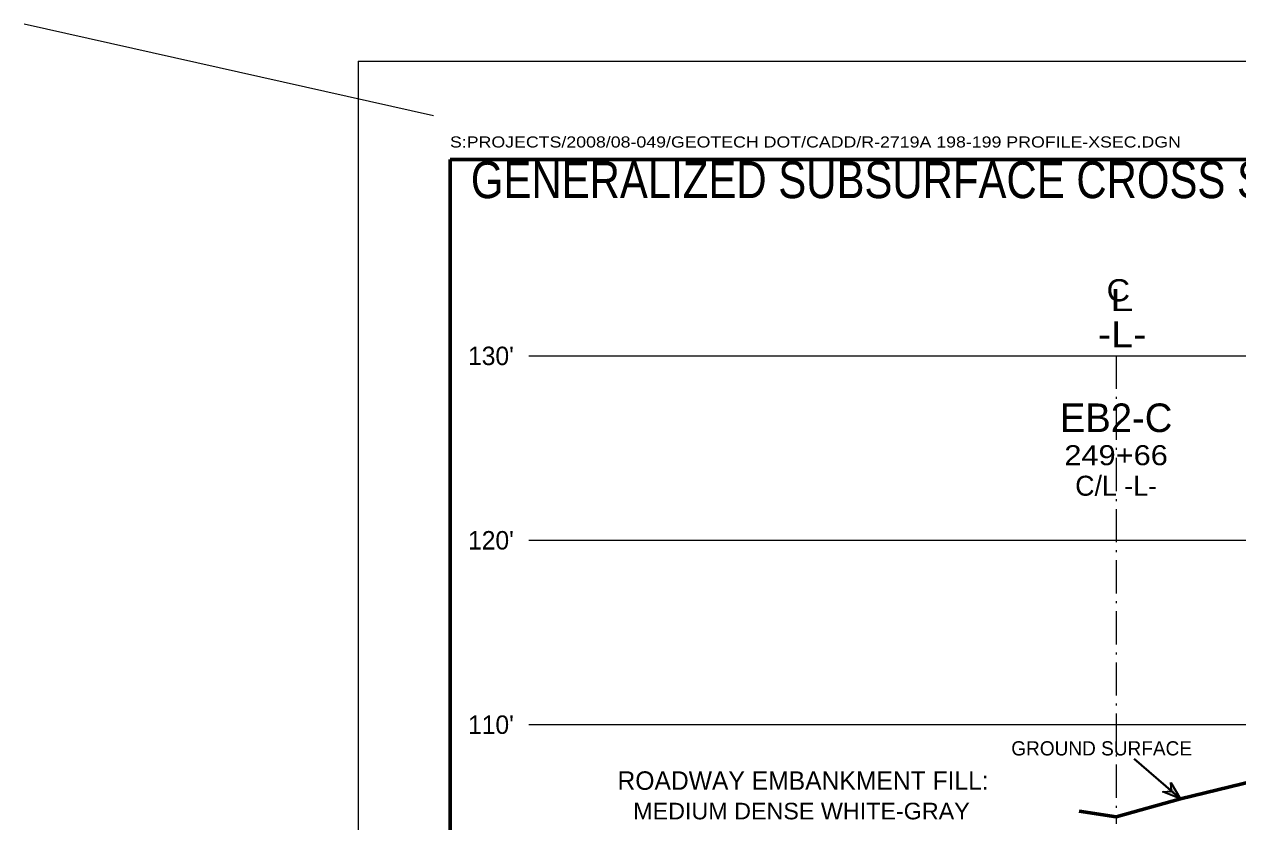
# Model space of a CAD drawing. Extents: x -76 to 974, y -1080 to -735.
# Drawn here: x 837.5 to 903.4, y -927.4 to -884.1 of the extents above; entities that cross this region are included whole.
import ezdxf
from ezdxf.enums import TextEntityAlignment as Align

# ---------------------------------------------------------------- set-up
doc = ezdxf.new("R2010")
doc.units = 0
doc.header["$LTSCALE"] = 0.36
doc.linetypes.add('DOT_DASHED', pattern=[7.7, 5, -1.2, 0.3, -1.2])
doc.linetypes.add('LONG_DASHED', pattern=[7.5, 6, -1.5])
for name, color, linetype, lineweight in [('10', 7, 'Continuous', 35), ('27', 7, 'Continuous', 40), ('28', 7, 'LONG_DASHED', 60), ('63', 7, 'Continuous', 35), ('7', 7, 'Continuous', 13)]:
    doc.layers.add(name, color=color, linetype=linetype, lineweight=lineweight)
doc.layers.add('29', color=7, linetype='Continuous')

msp = doc.modelspace()

# ---------------------------------------------------------------- hatches: boundary and pattern name
at = {"layer": '10'}
msp.add_hatch(color=256, dxfattribs=at).paths.add_polyline_path([(899.7198, -925.2326), (900.2574, -926.1302), (899.289, -925.7348), (899.7554, -925.699)])

# ---------------------------------------------------------------- linework, layer by layer
msp.add_lwpolyline([(899.7198, -925.2326), (900.2574, -926.1302), (899.289, -925.7348), (899.7554, -925.699)], close=True, dxfattribs=at)
at = {"layer": '27', "lineweight": 13}
msp.add_line((859.7247, -889.0898), (837.5348, -884.1181), dxfattribs=at)
at = {"layer": '27'}
msp.add_line((900.2577, -926.13), (897.7373, -923.9477), dxfattribs=at)
at = {"layer": '28', "linetype": 'Continuous'}
msp.add_lwpolyline([(894.7577, -926.79), (896.7577, -927.09), (900.2577, -926.13), (904.2577, -925.15), (927.7577, -925.74), (927.7577, -925.23), (931.7577, -925.24), (937.2577, -926.05), (942.7577, -926.96)], dxfattribs=at)
at = {"layer": '63', "lineweight": 13}
for q in [(855.6417, -1056.1123), (965.6417, -886.1123)]:
    msp.add_line((855.6417, -886.1123), q, dxfattribs=at)
at = {"layer": '63', "lineweight": 60}
for p in [(860.6417, -1052.1123), (960.6417, -891.4595)]:
    msp.add_line(p, (860.6417, -891.4595), dxfattribs=at)
at = {"layer": '7'}
for p, q in [((864.9092, -902.09), (956.2029, -902.09)), ((864.9092, -912.09), (956.2029, -912.09)), ((864.9092, -922.09), (956.2029, -922.09))]:
    msp.add_line(p, q, dxfattribs=at)
at = {"layer": '7', "linetype": 'DOT_DASHED'}
msp.add_line((896.7577, -902.09), (896.7577, -927.4789), dxfattribs=at)

# ---------------------------------------------------------------- texts
at = {"layer": '27'}
for s, width, p in [('C', 1.1, (896.2415, -899.1407)), ('L', 1.4, (896.4379, -899.6741))]:
    msp.add_text(s, height=1.2, dxfattribs=dict(at, width=width)).set_placement(p)
at = {"layer": '27', "width": 1.15}
for s, height, p in [('-L-', 1.4, (897.0842, -901.6327)), ('249+66', 1.085, (896.7586, -908.0288))]:
    msp.add_text(s, height=height, dxfattribs=at).set_placement(p, align=Align.CENTER)
at = {"layer": '27'}
for s, height, p in [('EB2-C', 1.55, (896.7577, -906.2324)), ('C/L -L-', 1.085, (896.7581, -909.6858)), ('GROUND SURFACE', 0.7717, (895.9742, -923.7701))]:
    msp.add_text(s, height=height, dxfattribs=at).set_placement(p, align=Align.CENTER)
at = {"layer": '29'}
msp.add_text('ROADWAY EMBANKMENT FILL:', height=1, dxfattribs=at).set_placement((879.7807, -925.6319), align=Align.CENTER)
at = {"layer": '29', "width": 1.05}
msp.add_text('MEDIUM DENSE WHITE-GRAY', height=0.9, dxfattribs=at).set_placement((879.6926, -927.2351), align=Align.CENTER)
at = {"layer": '63', "width": 1.2}
msp.add_text('S:PROJECTS/2008/08-049/GEOTECH DOT/CADD/R-2719A 198-199 PROFILE-XSEC.DGN', height=0.6, dxfattribs=at).set_placement((860.6253, -890.8007))
at = {"layer": '63', "width": 0.85}
msp.add_text('GENERALIZED SUBSURFACE CROSS SECTION THROUGH END BENT No. 2 (RIGHT LANE)', height=2, dxfattribs=at).set_placement((910.6417, -893.5476), align=Align.CENTER)
at = {"layer": '63'}
for s, p in [("130'", (862.8476, -902.6008)), ("120'", (862.8476, -912.6008)), ("110'", (862.8477, -922.6008))]:
    msp.add_text(s, height=1, dxfattribs=at).set_placement(p, align=Align.CENTER)

doc.saveas('drawing.dxf')
